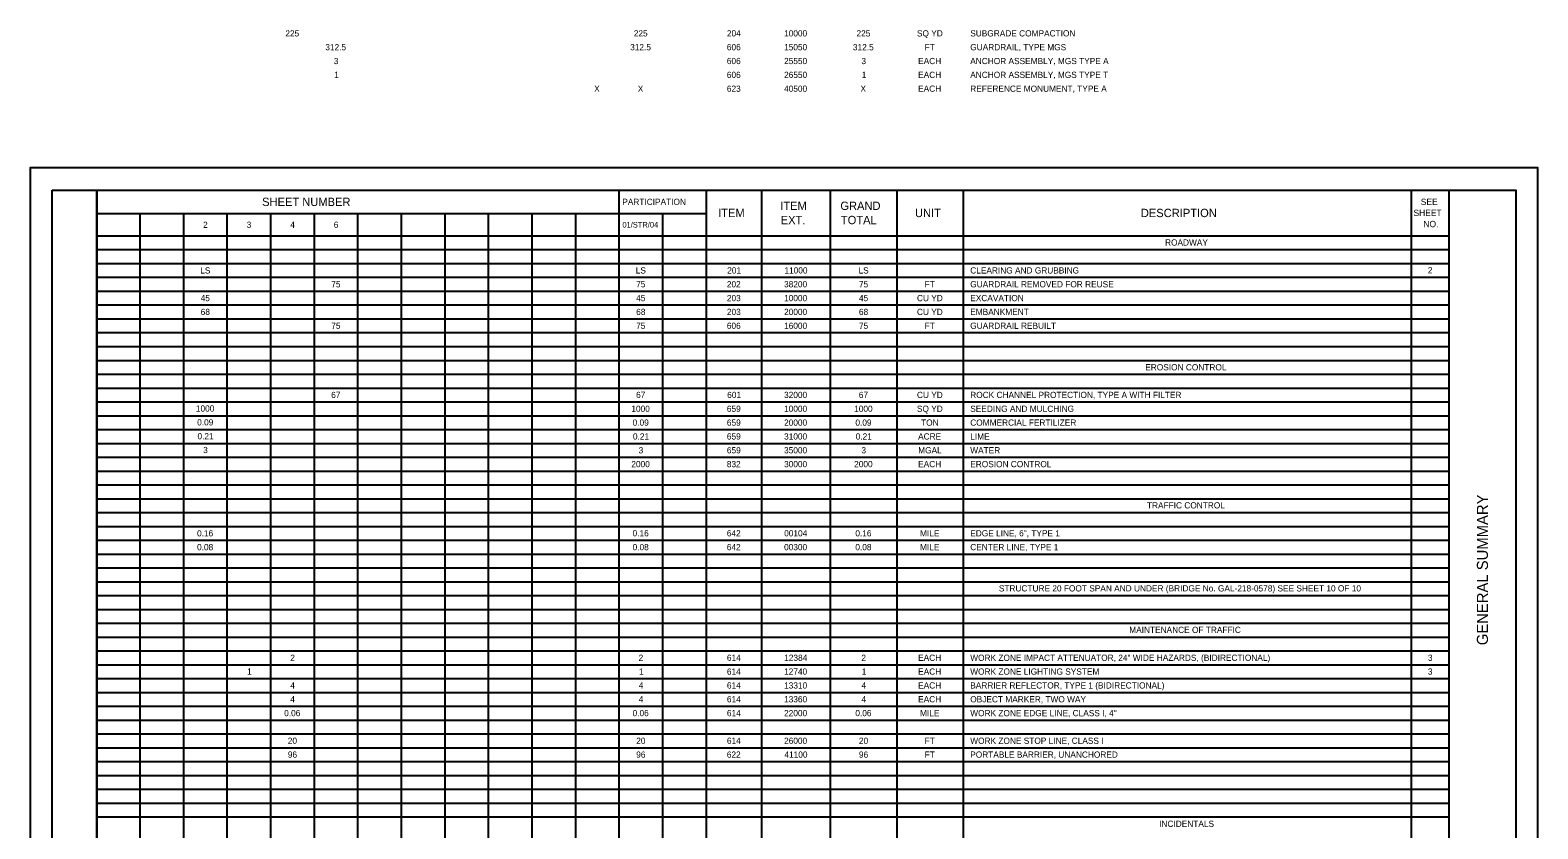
# Model space of a CAD drawing. Extents: x 0 to 34, y -10.8 to 25.1.
# Drawn here: x 0 to 34, y 7.09 to 25.11 of the extents above; entities that cross this region are included whole.
import ezdxf

# ---------------------------------------------------------------- set-up
doc = ezdxf.new("R2010")
doc.units = 0
for name, color, linetype in [('SH_Border', 7, 'Continuous'), ('SH_Cut_Line', 7, 'Continuous'), ('SH_Data', 7, 'Continuous'), ('TX_P_1', 7, 'Continuous')]:
    doc.layers.add(name, color=color, linetype=linetype)

msp = doc.modelspace()

# ---------------------------------------------------------------- linework, layer by layer
at = {"layer": 'SH_Border'}
msp.add_line((32, 0.5), (32, 21.5), dxfattribs=at)
msp.add_line((32, 0.5), (32, 21.5), dxfattribs=at)
for points in [[(0.5, 21.5), (1.5, 21.5), (1.5, 0.5), (0.5, 0.5)], [(1.5, 21.5), (33.5, 21.5), (33.5, 0.5), (1.5, 0.5)]]:
    msp.add_lwpolyline(points, close=True, dxfattribs=at)
at = {"layer": 'SH_Cut_Line'}
msp.add_lwpolyline([(0, 0), (34, 0), (34, 22), (0, 22)], close=True, dxfattribs=at)
at = {"layer": 'SH_Data'}
for p, q in [((13.286, 0.5), (13.286, 21.5)), ((15.25, 0.5), (15.25, 21.5)), ((16.5, 0.5), (16.5, 21.5)), ((18.05, 0.5), (18.05, 21.5)), ((19.55, 0.5), (19.55, 21.5)), ((21.05, 0.5), (21.05, 21.5)), ((31.15, 0.5), (31.15, 21.5)), ((1.5, 20.968), (15.25, 20.968)), ((2.482, 0.5), (2.482, 20.968)), ((3.464, 0.5), (3.464, 20.968)), ((4.446, 0.5), (4.446, 20.968)), ((5.429, 0.5), (5.429, 20.968)), ((6.411, 0.5), (6.411, 20.968)), ((7.393, 0.5), (7.393, 20.968)), ((8.375, 0.5), (8.375, 20.968)), ((9.357, 0.5), (9.357, 20.968)), ((10.339, 0.5), (10.339, 20.968)), ((11.321, 0.5), (11.321, 20.968)), ((12.304, 0.5), (12.304, 20.968)), ((14.268, 0.5), (14.268, 20.968)), ((1.5, 20.468), (32, 20.468)), ((1.5, 20.156), (32, 20.156)), ((1.5, 19.844), (32, 19.844)), ((1.5, 19.532), (32, 19.532)), ((1.5, 19.22), (32, 19.22)), ((1.5, 18.908), (32, 18.908)), ((1.5, 18.596), (32, 18.596)), ((1.5, 18.284), (32, 18.284)), ((1.5, 17.972), (32, 17.972)), ((1.5, 17.66), (32, 17.66)), ((1.5, 17.348), (32, 17.348)), ((1.5, 17.036), (32, 17.036)), ((1.5, 16.724), (32, 16.724)), ((1.5, 16.412), (32, 16.412)), ((1.5, 16.1), (32, 16.1)), ((1.5, 15.788), (32, 15.788)), ((1.5, 15.476), (32, 15.476)), ((1.5, 15.164), (32, 15.164)), ((1.5, 14.852), (32, 14.852)), ((1.5, 14.54), (32, 14.54)), ((1.5, 14.228), (32, 14.228)), ((1.5, 13.916), (32, 13.916)), ((1.5, 13.604), (32, 13.604)), ((1.5, 13.292), (32, 13.292)), ((1.5, 12.98), (32, 12.98)), ((1.5, 12.668), (32, 12.668)), ((1.5, 12.356), (32, 12.356)), ((1.5, 12.044), (32, 12.044)), ((1.5, 11.732), (32, 11.732)), ((1.5, 11.42), (32, 11.42)), ((1.5, 11.108), (32, 11.108)), ((1.5, 10.796), (32, 10.796)), ((1.5, 10.484), (32, 10.484)), ((1.5, 10.172), (32, 10.172)), ((1.5, 9.86), (32, 9.86)), ((1.5, 9.548), (32, 9.548)), ((1.5, 9.236), (32, 9.236)), ((1.5, 8.924), (32, 8.924)), ((1.5, 8.612), (32, 8.612)), ((1.5, 8.3), (32, 8.3)), ((1.5, 7.988), (32, 7.988)), ((1.5, 7.676), (32, 7.676)), ((1.5, 7.364), (32, 7.364))]:
    msp.add_line(p, q, dxfattribs=at)

# ---------------------------------------------------------------- texts
for s, height, p in [('SHEET NUMBER', 0.1875, (5.231, 21.14)), ('PARTICIPATION', 0.14, (13.353, 21.164)), ('ITEM', 0.1875, (16.915, 21.051)), ('GRAND', 0.1875, (18.271, 21.051)), ('DESCRIPTION', 0.1875, (25.047, 20.89)), ('SEE', 0.1426, (31.36, 21.162)), ('ITEM', 0.1875, (15.515, 20.89)), ('EXT.', 0.1875, (16.926, 20.73)), ('TOTAL', 0.1875, (18.283, 20.73)), ('UNIT', 0.1875, (19.954, 20.89)), ('SHEET', 0.1426, (31.195, 20.913)), ('NO.', 0.1426, (31.419, 20.663))]:
    msp.add_text(s, height=height, dxfattribs=at).set_placement(p)
msp.add_text('GENERAL SUMMARY', height=0.25, rotation=90, dxfattribs=at).set_placement((32.875, 11.235))
at = {"layer": 'TX_P_1'}
for s, height, p in [('225', 0.14, (5.755, 24.964)), ('225', 0.14, (13.612, 24.964)), ('204', 0.14, (15.713, 24.964)), ('10000', 0.14, (17.002, 24.964)), ('225', 0.14, (18.635, 24.964)), ('SQ YD', 0.14, (19.998, 24.964)), ('SUBGRADE COMPACTION', 0.14, (21.2, 24.964)), ('312.5', 0.14, (6.656, 24.652)), ('3', 0.14, (6.847, 24.34)), ('312.5', 0.14, (13.531, 24.652)), ('606', 0.14, (15.711, 24.652)), ('606', 0.14, (15.711, 24.34)), ('25550', 0.14, (17.002, 24.34)), ('15050', 0.14, (17.002, 24.652)), ('312.5', 0.14, (18.554, 24.652)), ('3', 0.14, (18.746, 24.34)), ('EACH', 0.14, (20.025, 24.34)), ('FT', 0.14, (20.171, 24.652)), ('ANCHOR ASSEMBLY, MGS TYPE A', 0.14, (21.2, 24.34)), ('GUARDRAIL, TYPE MGS', 0.14, (21.2, 24.652)), ('1', 0.14, (6.855, 24.028)), ('606', 0.14, (15.711, 24.028)), ('26550', 0.14, (17.002, 24.028)), ('1', 0.14, (18.753, 24.028)), ('EACH', 0.14, (20.025, 24.028)), ('ANCHOR ASSEMBLY, MGS TYPE T', 0.14, (21.2, 24.028)), ('X', 0.14, (12.719, 23.716)), ('X', 0.14, (13.702, 23.716)), ('623', 0.14, (15.712, 23.716)), ('40500', 0.14, (17.002, 23.716)), ('X', 0.14, (18.725, 23.716)), ('EACH', 0.14, (20.025, 23.716)), ('REFERENCE MONUMENT, TYPE A', 0.14, (21.2, 23.716)), ('2', 0.14, (3.9, 20.648)), ('3', 0.14, (4.883, 20.648)), ('4', 0.14, (5.866, 20.648)), ('6', 0.14, (6.846, 20.648)), ('01/STR/04', 0.126, (13.357, 20.655)), ('ROADWAY', 0.14, (25.593, 20.248)), ('LS', 0.14, (3.835, 19.618)), ('LS', 0.14, (13.657, 19.618)), ('201', 0.14, (15.719, 19.618)), ('11000', 0.14, (17.01, 19.618)), ('LS', 0.14, (18.68, 19.618)), ('CLEARING AND GRUBBING', 0.14, (21.2, 19.618)), ('2', 0.14, (31.52, 19.624)), ('75', 0.14, (6.791, 19.306)), ('75', 0.14, (13.666, 19.306)), ('202', 0.14, (15.711, 19.306)), ('38200', 0.14, (17.002, 19.306)), ('75', 0.14, (18.69, 19.306)), ('FT', 0.14, (20.171, 19.306)), ('GUARDRAIL REMOVED FOR REUSE', 0.14, (21.2, 19.306)), ('45', 0.14, (3.845, 18.994)), ('45', 0.14, (13.666, 18.994)), ('203', 0.14, (15.712, 18.994)), ('10000', 0.14, (17.002, 18.994)), ('45', 0.14, (18.69, 18.994)), ('CU YD', 0.14, (19.998, 18.994)), ('EXCAVATION', 0.14, (21.2, 18.994)), ('68', 0.14, (3.846, 18.682)), ('68', 0.14, (13.667, 18.682)), ('203', 0.14, (15.712, 18.682)), ('20000', 0.14, (17.002, 18.682)), ('68', 0.14, (18.69, 18.682)), ('CU YD', 0.14, (19.998, 18.682)), ('EMBANKMENT', 0.14, (21.2, 18.682)), ('75', 0.14, (6.791, 18.37)), ('75', 0.14, (13.666, 18.37)), ('606', 0.14, (15.711, 18.37)), ('16000', 0.14, (17.002, 18.37)), ('75', 0.14, (18.69, 18.37)), ('FT', 0.14, (20.171, 18.37)), ('GUARDRAIL REBUILT', 0.14, (21.2, 18.37)), ('EROSION CONTROL', 0.14, (25.147, 17.434)), ('67', 0.14, (6.789, 16.81)), ('67', 0.14, (13.664, 16.81)), ('601', 0.14, (15.719, 16.81)), ('32000', 0.14, (17.002, 16.81)), ('67', 0.14, (18.687, 16.81)), ('CU YD', 0.14, (19.998, 16.81)), ('ROCK CHANNEL PROTECTION, TYPE A WITH FILTER', 0.14, (21.2, 16.81)), ('1000', 0.14, (3.737, 16.504)), ('0.09', 0.14, (3.766, 16.192)), ('1000', 0.14, (13.558, 16.498)), ('0.09', 0.14, (13.587, 16.186)), ('659', 0.14, (15.712, 16.498)), ('659', 0.14, (15.712, 16.186)), ('20000', 0.14, (17.002, 16.186)), ('10000', 0.14, (17.002, 16.498)), ('1000', 0.14, (18.582, 16.498)), ('0.09', 0.14, (18.61, 16.186)), ('SQ YD', 0.14, (19.998, 16.498)), ('TON', 0.14, (20.092, 16.186)), ('SEEDING AND MULCHING', 0.14, (21.2, 16.498)), ('COMMERCIAL FERTILIZER', 0.14, (21.2, 16.186)), ('0.21', 0.14, (3.773, 15.88)), ('0.21', 0.14, (13.594, 15.874)), ('659', 0.14, (15.712, 15.874)), ('31000', 0.14, (17.002, 15.874)), ('0.21', 0.14, (18.617, 15.874)), ('ACRE', 0.14, (20.024, 15.874)), ('LIME', 0.14, (21.2, 15.874)), ('3', 0.14, (3.901, 15.568)), ('3', 0.14, (13.722, 15.562)), ('659', 0.14, (15.712, 15.562)), ('35000', 0.14, (17.002, 15.562)), ('3', 0.14, (18.746, 15.562)), ('MGAL', 0.14, (20.026, 15.562)), ('WATER', 0.14, (21.2, 15.562)), ('2000', 0.14, (13.558, 15.25)), ('832', 0.14, (15.711, 15.25)), ('30000', 0.14, (17.002, 15.25)), ('2000', 0.14, (18.582, 15.25)), ('EACH', 0.14, (20.025, 15.25)), ('EROSION CONTROL', 0.14, (21.2, 15.25)), ('TRAFFIC CONTROL', 0.14, (25.185, 14.32)), ('0.16', 0.14, (3.764, 13.69)), ('0.16', 0.14, (13.585, 13.69)), ('642', 0.14, (15.711, 13.69)), ('00104', 0.14, (17.004, 13.69)), ('0.16', 0.14, (18.609, 13.69)), ('MILE', 0.14, (20.067, 13.69)), ('EDGE LINE, 6", TYPE 1', 0.14, (21.2, 13.69)), ('0.08', 0.14, (3.764, 13.378)), ('0.08', 0.14, (13.586, 13.378)), ('642', 0.14, (15.711, 13.378)), ('00300', 0.14, (17.002, 13.378)), ('0.08', 0.14, (18.609, 13.378)), ('MILE', 0.14, (20.067, 13.378)), ('CENTER LINE, TYPE 1', 0.14, (21.2, 13.378)), ('STRUCTURE 20 FOOT SPAN AND UNDER (BRIDGE No. GAL-218-0578) SEE SHEET 10 OF 10', 0.14, (21.845, 12.448)), ('MAINTENANCE OF TRAFFIC', 0.14, (24.786, 11.512)), ('2', 0.14, (5.865, 10.883)), ('2', 0.14, (13.722, 10.883)), ('614', 0.14, (15.713, 10.883)), ('12384', 0.14, (17.004, 10.883)), ('2', 0.14, (18.745, 10.883)), ('EACH', 0.14, (20.025, 10.883)), ('WORK ZONE IMPACT ATTENUATOR, 24" WIDE HAZARDS, (BIDIRECTIONAL)', 0.14, (21.2, 10.883)), ('3', 0.14, (31.521, 10.883)), ('1', 0.14, (4.891, 10.571)), ('1', 0.14, (13.73, 10.571)), ('614', 0.14, (15.713, 10.571)), ('12740', 0.14, (17.002, 10.571)), ('1', 0.14, (18.753, 10.571)), ('EACH', 0.14, (20.025, 10.571)), ('WORK ZONE LIGHTING SYSTEM', 0.14, (21.2, 10.571)), ('3', 0.14, (31.521, 10.571)), ('4', 0.14, (5.866, 10.259)), ('4', 0.14, (13.724, 10.259)), ('614', 0.14, (15.713, 10.259)), ('13310', 0.14, (17.002, 10.259)), ('4', 0.14, (18.747, 10.259)), ('EACH', 0.14, (20.025, 10.259)), ('BARRIER REFLECTOR, TYPE 1 (BIDIRECTIONAL)', 0.14, (21.2, 10.259)), ('4', 0.14, (5.866, 9.947)), ('4', 0.14, (13.724, 9.947)), ('614', 0.14, (15.713, 9.947)), ('13360', 0.14, (17.002, 9.947)), ('4', 0.14, (18.747, 9.947)), ('EACH', 0.14, (20.025, 9.947)), ('OBJECT MARKER, TWO WAY', 0.14, (21.2, 9.947)), ('0.06', 0.14, (5.728, 9.635)), ('0.06', 0.14, (13.585, 9.635)), ('614', 0.14, (15.713, 9.635)), ('22000', 0.14, (17.002, 9.635)), ('0.06', 0.14, (18.609, 9.635)), ('MILE', 0.14, (20.067, 9.635)), ('WORK ZONE EDGE LINE, CLASS I, 4"', 0.14, (21.2, 9.635)), ('20', 0.14, (5.81, 9.011)), ('96', 0.14, (5.81, 8.699)), ('96', 0.14, (13.667, 8.699)), ('20', 0.14, (13.667, 9.011)), ('622', 0.14, (15.711, 8.699)), ('614', 0.14, (15.713, 9.011)), ('26000', 0.14, (17.002, 9.011)), ('41100', 0.14, (17.01, 8.699)), ('96', 0.14, (18.69, 8.699)), ('20', 0.14, (18.69, 9.011)), ('FT', 0.14, (20.171, 9.011)), ('WORK ZONE STOP LINE, CLASS I', 0.14, (21.2, 9.011)), ('PORTABLE BARRIER, UNANCHORED', 0.14, (21.2, 8.699)), ('FT', 0.14, (20.171, 8.699)), ('INCIDENTALS', 0.14, (25.46, 7.139))]:
    msp.add_text(s, height=height, dxfattribs=at).set_placement(p)

doc.saveas('drawing.dxf')
